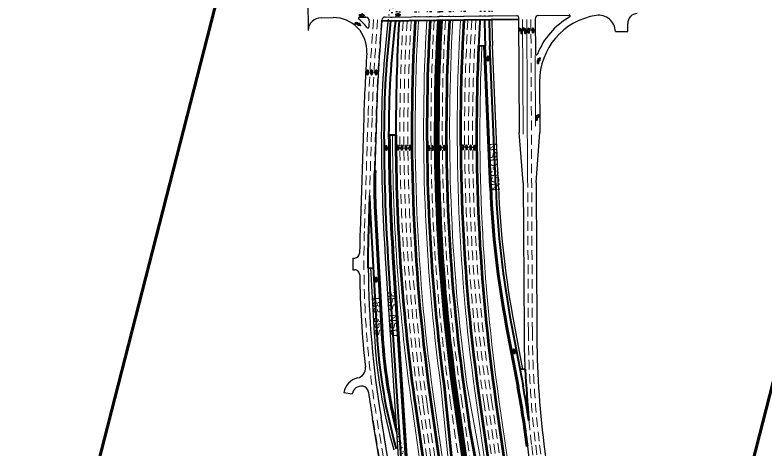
# Model space of a CAD drawing. Extents: x 2329387 to 2347382, y 6951580 to 6987999.
# Drawn here: x 2329419 to 2331668, y 6973752 to 6975053 of the extents above; entities that cross this region are included whole.
import ezdxf

# ---------------------------------------------------------------- set-up
doc = ezdxf.new("R2010")
doc.units = 0
doc.header["$LTSCALE"] = 9.6
doc.linetypes.add('DOTTED', pattern=[1.5, 0.3, -1.2])
doc.linetypes.add('MEDIUM_DASHED', pattern=[4.5, 3, -1.5])
for name, color, linetype, lineweight in [('26', 7, 'Continuous', 53), ('27', 7, 'Continuous', 40), ('28', 7, 'Continuous', 25), ('30', 7, 'Continuous', 13), ('41', 7, 'Continuous', 35), ('50', 7, 'MEDIUM_DASHED', 13), ('62', 7, 'Continuous', 60)]:
    doc.layers.add(name, color=color, linetype=linetype, lineweight=lineweight)
doc.layers.add('40', color=7, linetype='Continuous')

msp = doc.modelspace()

# ---------------------------------------------------------------- linework, layer by layer
at = {"layer": '26'}
for p, q in [((2330667.024, 6973887.048), (2331238.034, 6969888.911)), ((2330812.697, 6973892.639), (2331044.893, 6972266.831)), ((2330860.215, 6973899.425), (2331092.41, 6972273.627)), ((2330619.506, 6973880.262), (2330711.298, 6973237.549))]:
    msp.add_line(p, q, dxfattribs=at)
at = {"layer": '26', "lineweight": 13}
for p, q in [((2330676.924, 6973888.462), (2331247.933, 6969890.325)), ((2330802.797, 6973891.225), (2331034.992, 6972265.431)), ((2330870.114, 6973900.839), (2331102.309, 6972275.041)), ((2330609.607, 6973878.848), (2330701.398, 6973236.135))]:
    msp.add_line(p, q, dxfattribs=at)
at = {"layer": '26', "linetype": 'DOTTED'}
for centre, radius, start, end in [((2336379.635, 6974702.917), 5770.578, 175.12833, 176.70244), ((2336484.72, 6974702.711), 5729.578, 175.07558, 176.65104)]:
    msp.add_arc(centre, radius, start, end, dxfattribs=at)
at = {"layer": '26', "linetype": 'DOTTED', "lineweight": 13}
for centre, radius, start, end in [((2336379.635, 6974702.917), 5760.578, 175.11878, 176.69564), ((2336484.72, 6974702.711), 5739.578, 175.08526, 176.65796)]:
    msp.add_arc(centre, radius, start, end, dxfattribs=at)
at = {"layer": '26'}
for centre, radius, start, end in [((2336379.635, 6974702.917), 5770.578, 176.70244, 188.12796), ((2336484.72, 6974702.711), 5729.578, 176.65104, 188.12796), ((2336484.72, 6974702.711), 5681.578, 177.39461, 188.12795), ((2336379.635, 6974702.917), 5818.578, 180.09626, 188.12796)]:
    msp.add_arc(centre, radius, start, end, dxfattribs=at)
at = {"layer": '26', "lineweight": 13}
for centre, radius, start, end in [((2336379.635, 6974702.917), 5760.578, 176.69564, 188.12796), ((2336484.72, 6974702.711), 5739.578, 176.65796, 188.12796), ((2336484.72, 6974702.711), 5671.578, 177.39461, 188.12795), ((2336379.635, 6974702.917), 5828.578, 180.0962, 188.12796)]:
    msp.add_arc(centre, radius, start, end, dxfattribs=at)
at = {"layer": '27'}
for p, q in [((2330828.995, 6974960.069), (2330809.015, 6974960.978)), ((2330846.45, 6974537.493), (2330828.98, 6974960.411)), ((2330860.438, 6974538.071), (2330842.969, 6974960.985)), ((2330561.498, 6974693.143), (2330539.498, 6974693.117)), ((2330482.21, 6974511.671), (2330478.754, 6974403.639)), ((2330484.086, 6974462.412), (2330504.151, 6974099.871)), ((2330498.065, 6974463.186), (2330518.129, 6974100.644)), ((2330537.493, 6974325.221), (2330581.709, 6973635.66)), ((2330551.464, 6974326.117), (2330595.68, 6973636.556)), ((2330477.359, 6974294.779), (2330493.358, 6974294.88)), ((2330894.135, 6974121.368), (2330928.548, 6973939.398)), ((2330907.891, 6974123.97), (2330942.304, 6973942)), ((2330949.164, 6973991.39), (2330933.098, 6973990.681))]:
    msp.add_line(p, q, dxfattribs=at)
at = {"layer": '27', "lineweight": 25}
for p, q in [((2330842.454, 6974537.319), (2330824.984, 6974960.251)), ((2330868.431, 6974538.406), (2330850.962, 6974961.318)), ((2330500.621, 6974586.789), (2330496.623, 6974586.916)), ((2330502.059, 6974463.407), (2330522.123, 6974100.865)), ((2330485.349, 6974294.829), (2330496.163, 6974099.429)), ((2330890.204, 6974120.625), (2330924.617, 6973938.655)), ((2330915.751, 6974125.457), (2330941.172, 6973991.037))]:
    msp.add_line(p, q, dxfattribs=at)
at = {"layer": '27', "linetype": 'DOTTED'}
msp.add_line((2330596.795, 6973681.691), (2330575.693, 6973756.218), dxfattribs=at)
at = {"layer": '27', "linetype": 'DOTTED', "lineweight": 25}
msp.add_line((2330595.577, 6973700.673), (2330579.542, 6973757.308), dxfattribs=at)
at = {"layer": '27', "lineweight": 13}
msp.add_line((2330956.506, 6973760.674), (2330952.536, 6973760.182), dxfattribs=at)
at = {"layer": '27', "lineweight": 25}
for points in [[(2330529.51, 6974324.709), (2330568.734, 6973712.99), (2330573.726, 6973635.148)], [(2330555.456, 6974326.373), (2330593.593, 6973731.615), (2330599.672, 6973636.812)]]:
    msp.add_lwpolyline(points, dxfattribs=at)
at = {"layer": '27', "linetype": 'DOTTED', "lineweight": 25}
for centre, radius, start, end in [((2333390.285, 6974696.408), 2872.789, 169.67966, 173.25178), ((2333705.317, 6975079.218), 2856.789, 177.67031, 180.8204), ((2332101.706, 6974188.285), 1582, 193.18193, 195.80865)]:
    msp.add_arc(centre, radius, start, end, dxfattribs=at)
at = {"layer": '27', "linetype": 'DOTTED'}
for centre, radius, start, end in [((2333390.285, 6974696.408), 2864.789, 169.79291, 173.23111), ((2336484.72, 6974702.711), 5681.578, 175.02864, 176.61751), ((2333705.317, 6975079.218), 2878.789, 177.69282, 180.81882), ((2333705.317, 6975079.218), 2864.789, 177.67854, 180.81982), ((2333390.285, 6974696.408), 2850.789, 170.27054, 173.19465), ((2336379.635, 6974702.917), 5818.578, 175.31484, 176.73475), ((2332101.706, 6974188.285), 1586, 194.00868, 195.80865)]:
    msp.add_arc(centre, radius, start, end, dxfattribs=at)
at = {"layer": '27', "lineweight": 25}
for centre, radius, start, end in [((2333390.285, 6974696.408), 2872.789, 173.25178, 180.06614), ((2333705.317, 6975079.218), 2856.789, 180.8204, 182.36528), ((2336380.072, 6974699.86), 5862.578, 180.06614, 183.66891), ((2336380.072, 6974699.86), 5836.578, 180.06614, 183.66891), ((2331914.292, 6974541.565), 1414.394, 178.16771, 183.16771), ((2333722.786, 6974656.305), 2882.789, 182.36516, 190.70895), ((2333722.786, 6974656.305), 2856.789, 182.36525, 190.70895), ((2332101.706, 6974188.285), 1608, 183.16771, 195.80865), ((2332101.706, 6974188.285), 1582, 183.16771, 193.18193), ((2328127.409, 6973409.665), 2846.789, 7.07261, 10.70895)]:
    msp.add_arc(centre, radius, start, end, dxfattribs=at)
at = {"layer": '27'}
for centre, radius, start, end in [((2333390.285, 6974696.408), 2864.789, 173.23111, 180.06614), ((2333390.285, 6974696.408), 2850.789, 173.19465, 180.06614), ((2336379.635, 6974702.917), 5818.578, 176.73476, 180.09626), ((2336484.72, 6974702.711), 5681.578, 176.61751, 177.39462), ((2333705.317, 6975079.218), 2878.789, 180.81882, 182.36526), ((2333705.317, 6975079.218), 2864.789, 180.81982, 182.36535), ((2336380.072, 6974699.86), 5854.578, 180.06614, 183.66891), ((2336380.072, 6974699.86), 5840.578, 180.06614, 183.66891), ((2331914.292, 6974541.565), 1418.394, 178.16771, 183.16771), ((2333722.786, 6974656.305), 2878.789, 182.36535, 190.70895), ((2333722.786, 6974656.305), 2864.789, 182.36535, 190.70895), ((2331914.292, 6974541.565), 1432.394, 181.19582, 183.16771), ((2333318.09, 6974312.808), 2840.789, 178.16771, 180.36364), ((2332101.706, 6974188.285), 1600, 183.16771, 195.80865), ((2332101.706, 6974188.285), 1586, 183.16771, 194.00868), ((2333847.131, 6974119.317), 2900.789, 182.52762, 185.57282), ((2328127.409, 6973409.665), 2850.789, 7.07261, 10.70895), ((2328127.409, 6973409.665), 2864.789, 8.59126, 10.70895), ((2328127.409, 6973409.665), 2864.789, 8.59126, 8.83126)]:
    msp.add_arc(centre, radius, start, end, dxfattribs=at)
at = {"layer": '28'}
for p, q in [((2330296.752, 6975096.406), (2330297.71, 6975006.947)), ((2330337.226, 6975044.837), (2330373.174, 6975045.222)), ((2330452.011, 6975046.066), (2330471.032, 6975046.27)), ((2330519.178, 6975034.785), (2330929.004, 6975039.173)), ((2330519.342, 6975036.786), (2330928.995, 6975041.173)), ((2330529.277, 6975046.893), (2330923.918, 6975051.119)), ((2330928.971, 6975046.143), (2330930.588, 6974700.753)), ((2330978.992, 6975041.769), (2330979.486, 6974936.315)), ((2330988.885, 6975051.815), (2331081.037, 6975052.802)), ((2331256.808, 6975011.988), (2331256.42, 6975027.039)), ((2330991.876, 6974853.041), (2330992.499, 6974719.86)), ((2330464.675, 6974745.425), (2330453.767, 6974404.439)), ((2330502.655, 6974744.21), (2330497.623, 6974586.884)), ((2330992.499, 6974719.86), (2330992.588, 6974701.043)), ((2330943.29, 6974550.81), (2330930.588, 6974700.753)), ((2330981.29, 6974550.988), (2330992.588, 6974701.043)), ((2330943.29, 6974550.81), (2330945.374, 6974105.734)), ((2330981.29, 6974550.988), (2330983.373, 6974105.912)), ((2330432.256, 6974324.557), (2330437.68, 6974324.649)), ((2330432.331, 6974288.977), (2330437.308, 6974289.062)), ((2330404.668, 6973921.69), (2330430.292, 6973917.283)), ((2330881.902, 6971488.571), (2330490.933, 6973843.423)), ((2330735.162, 6972531.567), (2330516.65, 6973847.693)), ((2330955.513, 6973760.551), (2331139.44, 6972278.125)), ((2331005.133, 6973766.707), (2331297.68, 6971408.806))]:
    msp.add_line(p, q, dxfattribs=at)
msp.add_lwpolyline([(2331219.463, 6975003.586), (2331256.184, 6975003.933), (2331256.808, 6975011.988)], dxfattribs=at)
for centre, radius, start, end in [((2331286.41, 6975027.813), 30, 92.49207, 181.47799), ((2330337.654, 6975004.839), 40, 90.61353, 176.97952), ((2330374.245, 6974945.228), 100, 356.28848, 90.61353), ((2330452.043, 6975043.066), 3, 90.61353, 231.50931), ((2330374.245, 6974945.228), 122, 35.01482, 51.50931), ((2330471.14, 6975036.27), 10, 355.3471, 90.61353), ((2336363.235, 6974556.728), 5901.578, 175.3471, 175.52963), ((2336363.235, 6974556.728), 5863.578, 175.29477, 178.16771), ((2330529.385, 6975036.894), 10, 90.61353, 175.29477), ((2330923.972, 6975046.12), 5, 0.2682, 90.61353), ((2330988.992, 6975041.816), 10, 90.61353, 180.2682), ((2331191.874, 6974853.977), 222, 119.50274, 158.53047), ((2331191.874, 6974853.977), 200, 98.58598, 180.2682), ((2331081.069, 6975049.802), 3, 299.50274, 90.61353), ((2331169.48, 6975002.296), 50, 1.478, 98.58598), ((2330476.62, 6975016.951), 3, 215.01482, 355.52963), ((2336363.235, 6974556.728), 5901.578, 176.28848, 178.16771), ((2330982.486, 6974936.329), 3, 180.2682, 338.53047), ((2333318.09, 6974312.808), 2865.789, 178.16771, 179.4662), ((2330437.426, 6974339.647), 15, 270.96844, 359.4662), ((2333318.09, 6974312.808), 2885.858, 179.76673, 180.47314), ((2333318.09, 6974312.808), 2839.789, 180.36364, 189.42666), ((2330437.562, 6974274.064), 15, 0.77061, 90.96844), ((2333318.09, 6974312.808), 2865.789, 180.77061, 186.30928), ((2333847.131, 6974119.317), 2901.789, 180.2682, 182.52762), ((2333847.131, 6974119.317), 2863.789, 180.2682, 187.07261), ((2330439.841, 6973994.575), 30, 282.40576, 6.30928), ((2330457.887, 6973912.536), 54, 102.40576, 170.2397), ((2330457.887, 6973912.536), 28, 81.27938, 170.2397), ((2330459.1, 6973920.444), 20, 7.81439, 81.27938), ((2333318.09, 6974312.808), 2865.789, 187.81439, 189.42666)]:
    msp.add_arc(centre, radius, start, end, dxfattribs=at)
at = {"layer": '30', "lineweight": 53}
for p, q in [((2330705.864, 6973941.734), (2330736.221, 6973643.023)), ((2330735.905, 6973899.861), (2331296.241, 6969976.458)), ((2330745.804, 6973901.275), (2331470.823, 6968824.782)), ((2330769.563, 6973904.668), (2330780.775, 6973826.162)), ((2330835.07, 6973530.872), (2330780.775, 6973826.162))]:
    msp.add_line(p, q, dxfattribs=at)
at = {"layer": '30'}
for p, q in [((2330773.194, 6973951.266), (2330849.877, 6973533.29)), ((2330739.864, 6973900.426), (2331300.2, 6969977.023)), ((2330741.844, 6973900.709), (2331466.866, 6968824.195))]:
    msp.add_line(p, q, dxfattribs=at)
msp.add_lwpolyline([(2330695.932, 6973940.561), (2330726.292, 6973641.81), (2330768.736, 6973344.623)], dxfattribs=at)
at = {"layer": '30', "linetype": 'DOTTED'}
for radius, start, end in [(5768.578, 175.19992, 176.76446), (5730.578, 175.16391, 176.7389), (5728.578, 175.16201, 176.73754), (5690.578, 175.12549, 176.71162)]:
    msp.add_arc((2336412.878, 6974710.64), radius, start, end, dxfattribs=at)
at = {"layer": '30', "linetype": 'DOTTED', "lineweight": 53}
for radius, start, end in [(5758.578, 175.19049, 176.75777), (5734.578, 175.17429, 176.74161), (5724.578, 175.15818, 176.73483), (5700.578, 175.13515, 176.71848)]:
    msp.add_arc((2336412.878, 6974710.64), radius, start, end, dxfattribs=at)
at = {"layer": '30'}
for radius, start, end in [(5768.578, 176.76446, 187.67163), (5730.578, 176.7389, 188.12796), (5728.578, 176.73754, 188.12795), (5690.578, 176.71162, 187.66865)]:
    msp.add_arc((2336412.878, 6974710.64), radius, start, end, dxfattribs=at)
at = {"layer": '30', "lineweight": 53}
for radius, start, end in [(5758.578, 176.75777, 187.67326), (5734.578, 176.74161, 188.12795), (5724.578, 176.73483, 188.12796), (5700.578, 176.71848, 188.12796)]:
    msp.add_arc((2336412.878, 6974710.64), radius, start, end, dxfattribs=at)
at = {"layer": '41'}
for points in [[(2330452.242, 6975050.653), (2330452.232, 6975053.654), (2330459.039, 6975053.678), (2330459.03, 6975056.115), (2330466.243, 6975052.362), (2330459.057, 6975048.558), (2330459.049, 6975050.677)], [(2330560.947, 6975052.228), (2330560.936, 6975055.229), (2330567.743, 6975055.253), (2330567.734, 6975057.69), (2330574.947, 6975053.937), (2330567.761, 6975050.133), (2330567.753, 6975052.252)], [(2330438.676, 6975029.069), (2330446.619, 6975029.138), (2330450.084, 6975026.449), (2330451.501, 6975028.432), (2330455.163, 6975021.173), (2330447.108, 6975022.282), (2330448.34, 6975024.007), (2330445.607, 6975026.128), (2330438.702, 6975026.068)], [(2330939.42, 6974997.126), (2330939.319, 6975005.07), (2330936.557, 6975008.476), (2330938.509, 6975009.935), (2330931.173, 6975013.441), (2330932.455, 6975005.411), (2330934.153, 6975006.68), (2330936.332, 6975003.993), (2330936.42, 6974997.088)], [(2330950.775, 6974997.795), (2330950.674, 6975005.738), (2330947.912, 6975009.144), (2330949.864, 6975010.603), (2330942.528, 6975014.109), (2330943.81, 6975006.08), (2330945.508, 6975007.348), (2330947.687, 6975004.661), (2330947.775, 6974997.756)], [(2330958.043, 6974999.304), (2330961.044, 6974999.319), (2330961.011, 6975006.126), (2330963.448, 6975006.138), (2330959.634, 6975013.319), (2330955.89, 6975006.101), (2330958.01, 6975006.111)], [(2330970.593, 6974999.626), (2330973.594, 6974999.64), (2330973.56, 6975006.447), (2330975.998, 6975006.459), (2330972.183, 6975013.641), (2330968.44, 6975006.422), (2330970.56, 6975006.432)], [(2330835.814, 6974916.007), (2330838.814, 6974916.085), (2330838.637, 6974922.889), (2330841.073, 6974922.953), (2330837.108, 6974930.052), (2330833.518, 6974922.756), (2330835.637, 6974922.811)], [(2330985.927, 6974907.972), (2330985.927, 6974915.916), (2330988.646, 6974919.357), (2330986.675, 6974920.791), (2330993.966, 6974924.391), (2330992.786, 6974916.345), (2330991.072, 6974917.592), (2330988.927, 6974914.878), (2330988.927, 6974907.972)], [(2330477.903, 6974887.525), (2330474.903, 6974887.574), (2330474.792, 6974880.768), (2330472.355, 6974880.808), (2330476.016, 6974873.547), (2330479.912, 6974880.684), (2330477.792, 6974880.719)], [(2330490.145, 6974887.42), (2330487.144, 6974887.469), (2330487.033, 6974880.663), (2330484.596, 6974880.703), (2330488.257, 6974873.442), (2330492.153, 6974880.579), (2330490.034, 6974880.614)], [(2330503.61, 6974887.304), (2330500.609, 6974887.353), (2330500.498, 6974880.547), (2330498.061, 6974880.587), (2330501.722, 6974873.326), (2330505.618, 6974880.464), (2330503.499, 6974880.498)], [(2330981.425, 6974737.756), (2330981.425, 6974745.7), (2330984.144, 6974749.141), (2330982.173, 6974750.575), (2330989.465, 6974754.175), (2330988.285, 6974746.129), (2330986.571, 6974747.376), (2330984.426, 6974744.662), (2330984.426, 6974737.756)], [(2330534.343, 6974661.426), (2330531.342, 6974661.409), (2330531.379, 6974654.603), (2330528.942, 6974654.59), (2330532.759, 6974647.41), (2330536.499, 6974654.631), (2330534.38, 6974654.619)], [(2330569.255, 6974662.043), (2330566.255, 6974662.026), (2330566.292, 6974655.22), (2330563.854, 6974655.206), (2330567.672, 6974648.027), (2330571.412, 6974655.248), (2330569.292, 6974655.236)], [(2330580.495, 6974662.178), (2330577.494, 6974662.161), (2330577.531, 6974655.355), (2330575.094, 6974655.341), (2330578.912, 6974648.162), (2330582.651, 6974655.383), (2330580.532, 6974655.371)], [(2330593.309, 6974661.721), (2330590.308, 6974661.705), (2330590.345, 6974654.899), (2330587.908, 6974654.885), (2330591.726, 6974647.706), (2330595.466, 6974654.926), (2330593.346, 6974654.915)], [(2330604.548, 6974661.856), (2330601.548, 6974661.84), (2330601.585, 6974655.034), (2330599.147, 6974655.02), (2330602.965, 6974647.841), (2330606.705, 6974655.061), (2330604.585, 6974655.05)], [(2330662.142, 6974660.988), (2330659.141, 6974660.971), (2330659.178, 6974654.165), (2330656.741, 6974654.151), (2330660.559, 6974646.972), (2330664.299, 6974654.192), (2330662.179, 6974654.181)], [(2330673.381, 6974661.123), (2330670.381, 6974661.106), (2330670.418, 6974654.3), (2330667.98, 6974654.286), (2330671.798, 6974647.107), (2330675.538, 6974654.327), (2330673.418, 6974654.316)], [(2330692.656, 6974647.958), (2330695.656, 6974647.974), (2330695.619, 6974654.781), (2330698.057, 6974654.794), (2330694.239, 6974661.974), (2330690.499, 6974654.753), (2330692.619, 6974654.764)], [(2330704.563, 6974648.055), (2330707.564, 6974648.072), (2330707.527, 6974654.878), (2330709.964, 6974654.892), (2330706.146, 6974662.071), (2330702.406, 6974654.85), (2330704.526, 6974654.862)], [(2330760.248, 6974649.547), (2330763.249, 6974649.561), (2330763.215, 6974656.368), (2330765.653, 6974656.38), (2330761.838, 6974663.561), (2330758.095, 6974656.343), (2330760.215, 6974656.353)], [(2330771.538, 6974649.551), (2330774.539, 6974649.565), (2330774.505, 6974656.372), (2330776.942, 6974656.384), (2330773.128, 6974663.565), (2330769.385, 6974656.347), (2330771.504, 6974656.357)], [(2330783.728, 6974649.019), (2330786.729, 6974649.034), (2330786.696, 6974655.84), (2330789.133, 6974655.852), (2330785.319, 6974663.034), (2330781.575, 6974655.815), (2330783.695, 6974655.826)], [(2330795.116, 6974648.837), (2330798.116, 6974648.852), (2330798.083, 6974655.659), (2330800.52, 6974655.671), (2330796.706, 6974662.852), (2330792.963, 6974655.633), (2330795.082, 6974655.644)], [(2330503.757, 6974266.732), (2330500.765, 6974266.508), (2330501.273, 6974259.72), (2330498.843, 6974259.538), (2330503.149, 6974252.64), (2330506.379, 6974260.103), (2330504.266, 6974259.944)], [(2330915.598, 6974038.057), (2330918.532, 6974038.684), (2330917.111, 6974045.34), (2330919.495, 6974045.849), (2330914.296, 6974052.102), (2330912.104, 6974044.271), (2330914.177, 6974044.714)]]:
    msp.add_lwpolyline(points, close=True, dxfattribs=at)
at = {"layer": '50'}
for p, q in [((2330451.023, 6975047.056), (2330470.838, 6975047.268)), ((2330966.004, 6975039.358), (2330970.373, 6974105.851)), ((2330477.668, 6974745.009), (2330466.76, 6974404.023)), ((2330489.662, 6974744.625), (2330482.21, 6974511.671)), ((2330501.656, 6974744.242), (2330496.623, 6974586.916)), ((2330956.227, 6974564.456), (2330958.374, 6974105.795)), ((2330655.145, 6973885.352), (2331630.147, 6967058.504)), ((2330724.025, 6973898.164), (2331204.555, 6970533.55)), ((2330757.684, 6973902.971), (2331482.703, 6968826.479)), ((2330824.576, 6973894.335), (2331056.771, 6972268.537)), ((2330836.456, 6973896.032), (2331068.651, 6972270.233)), ((2330848.335, 6973897.729), (2331080.528, 6972271.946)), ((2330631.386, 6973881.958), (2331606.386, 6967055.128)), ((2330643.265, 6973883.655), (2331618.272, 6967056.781)), ((2330879.702, 6971508.348), (2330491.987, 6973843.598)), ((2330891.543, 6971510.297), (2330503.823, 6973845.574)), ((2330734.176, 6972531.404), (2330515.663, 6973847.529)), ((2330968.414, 6973762.152), (2331057.653, 6973042.894)), ((2330980.323, 6973763.629), (2331164.249, 6972281.203)), ((2330992.232, 6973765.107), (2331284.779, 6971407.206))]:
    msp.add_line(p, q, dxfattribs=at)
at = {"layer": '50', "linetype": 'Continuous'}
for p, q in [((2330941.004, 6975039.302), (2330942.609, 6974696.368)), ((2330954.004, 6975039.302), (2330956.227, 6974564.457)), ((2330978.509, 6974931.415), (2330979.5, 6974719.799))]:
    msp.add_line(p, q, dxfattribs=at)
at = {"layer": '50'}
for centre, radius, start, end in [((2336363.235, 6974556.728), 5888.578, 175.29477, 178.16771), ((2336363.235, 6974556.728), 5876.578, 175.29477, 178.16771), ((2336363.235, 6974556.728), 5864.578, 175.29477, 178.16771), ((2336379.635, 6974702.917), 5806.578, 176.72672, 188.12795), ((2336379.635, 6974702.917), 5794.578, 176.71866, 188.12795), ((2336379.635, 6974702.917), 5782.578, 176.71057, 188.12796), ((2336412.878, 6974710.64), 5746.578, 176.74971, 188.12796), ((2336412.878, 6974710.64), 5712.578, 176.72667, 188.12795), ((2336484.72, 6974702.711), 5717.578, 176.64271, 188.12796), ((2336484.72, 6974702.711), 5705.578, 176.63435, 188.12796), ((2336484.72, 6974702.711), 5693.578, 176.62594, 188.12795), ((2333318.09, 6974312.808), 2852.789, 178.16771, 189.42666), ((2333847.131, 6974119.317), 2888.789, 180.2682, 187.07261), ((2333847.131, 6974119.317), 2876.789, 180.2682, 187.07261), ((2333847.131, 6974119.317), 2900.789, 185.57282, 187.07262)]:
    msp.add_arc(centre, radius, start, end, dxfattribs=at)
at = {"layer": '62'}
msp.add_lwpolyline([(2333194.662, 6979814.447), (2331455.123, 6973029.722), (2329419.111, 6972738.941), (2331377.669, 6980377.903)], close=True, dxfattribs=at)

# ---------------------------------------------------------------- texts
at = {"layer": '40', "width": 1.05}
msp.add_text('NSD-35N', height=24, rotation=275.212, dxfattribs=at).set_placement((2330836.945, 6974668.518))
at = {"layer": '40'}
for s, rotation, p in [('35S-NSD', 275.022, (2330535.2, 6974222.96)), ('183-35S', 273.739, (2330490.951, 6974211.806))]:
    msp.add_text(s, height=24, rotation=rotation, dxfattribs=at).set_placement(p)

doc.saveas('drawing.dxf')
